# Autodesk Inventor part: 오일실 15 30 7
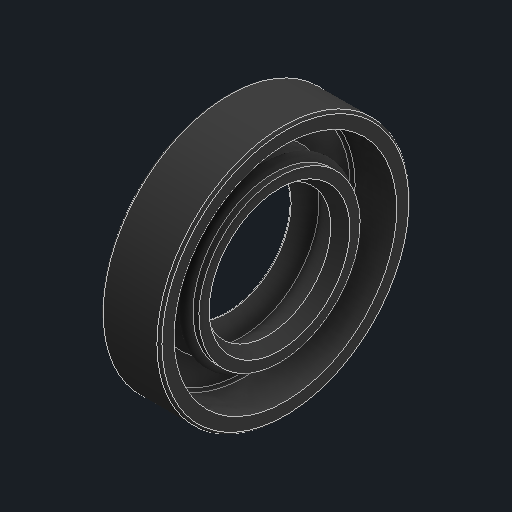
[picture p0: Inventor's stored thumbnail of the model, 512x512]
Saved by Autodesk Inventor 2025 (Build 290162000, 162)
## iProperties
Created: 2025-08
Part Number: 오일실 15 30 7
Material: 고무
Description: 오일-실
Document SubType Name: Modeling
Designer: infra006
Density: 0.93 g/cm^3
Appearance: 기본값
Author: jhkim
Sending System: Autodesk Inventor 2026
Preprocessor: ST-DEVELOPER v20.1
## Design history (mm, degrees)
feature "Solid1"
node "솔리드1"
